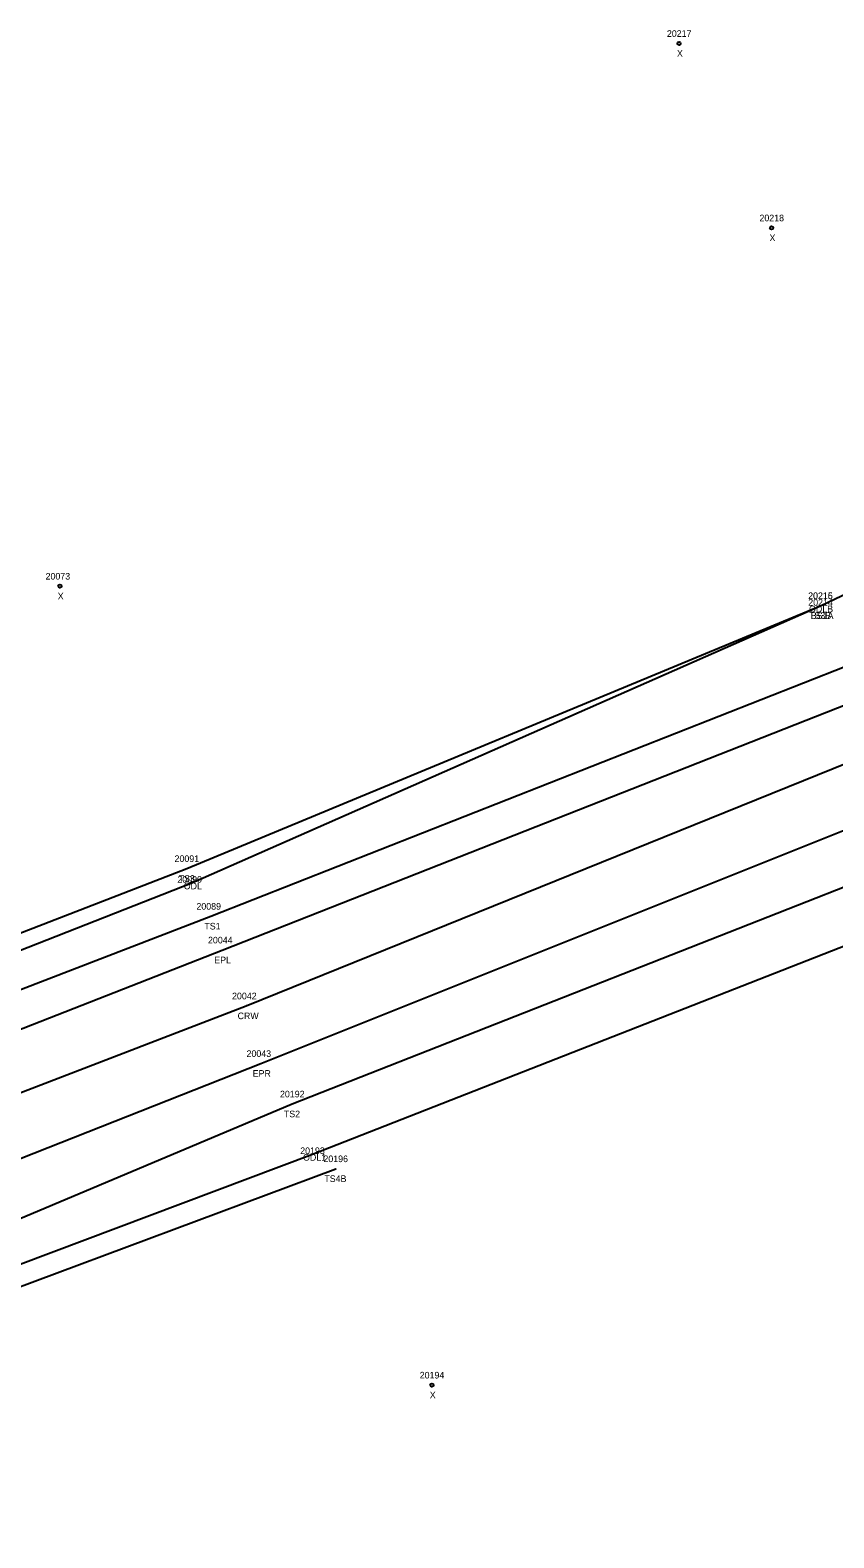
# Model space of a CAD drawing. Extents: x 1966740 to 1969291, y 1117378 to 1118461.
# Drawn here: x 1967441.2 to 1967562.8, y 1117652.7 to 1117880.7 of the extents above; entities that cross this region are included whole.
import ezdxf

# ---------------------------------------------------------------- set-up
doc = ezdxf.new("R2010")
doc.units = 0
for name, color, linetype in [('RD_DTM_BkLn1', 7, 'Continuous'), ('RD_DTM_BkLn2', 7, 'Continuous'), ('RD_EX_H2O', 7, 'Continuous'), ('RD_EX_H2O_txCode', 7, 'Continuous'), ('RD_EX_Road', 7, 'Continuous'), ('RD_EX_Road_txCode', 7, 'Continuous'), ('RD_SMD_Locator', 7, 'Continuous'), ('RD_SMD_Misc', 7, 'Continuous')]:
    doc.layers.add(name, color=color, linetype=linetype)

msp = doc.modelspace()

# ---------------------------------------------------------------- linework, layer by layer
at = {"layer": 'RD_DTM_BkLn1'}
msp.add_lwpolyline([(1966772.57, 1117449.88), (1966874.49, 1117489.87), (1966974.64, 1117529.93), (1967075.06, 1117571.68), (1967175.91, 1117613.34), (1967274.11, 1117653.69), (1967325.25, 1117674.8), (1967374.73, 1117695), (1967473.9, 1117733.1), (1967569.8, 1117771.9), (1967665.19, 1117809.79), (1967697.89, 1117822.8)], dxfattribs=at)
at = {"layer": 'RD_DTM_BkLn2'}
for points in [[(1967560.73, 1117793.63), (1967650.63, 1117836.46), (1967680.95, 1117850.94), (1967690.95, 1117852.56), (1967700.5, 1117839.06)], [(1966768.15, 1117461.43), (1966869.41, 1117499.34), (1967070.52, 1117582.35), (1967171.25, 1117624.02), (1967269.74, 1117664.9), (1967320.21, 1117685.71), (1967369.37, 1117708.48), (1967468.51, 1117746.66), (1967564.6, 1117784.47), (1967654.68, 1117828.05), (1967680.1, 1117841.48), (1967687.91, 1117842.93), (1967691.45, 1117838.71), (1967693.03, 1117834.22)], [(1967334.06, 1117655.75), (1967334.81, 1117659.44), (1967379.1, 1117675.46), (1967480.83, 1117718.27), (1967577.81, 1117756.42), (1967702.07, 1117801.85), (1967703.17, 1117805.75), (1967702.89, 1117809.87)], [(1966766.42, 1117472.19), (1966865.47, 1117508.82), (1967066.64, 1117593.45), (1967166.55, 1117636.11), (1967264.62, 1117677.56), (1967315.66, 1117698.57), (1967367.9, 1117716.34), (1967464.92, 1117753.87), (1967560.73, 1117793.63)], [(1967334.06, 1117655.75), (1967336.84, 1117652.84), (1967381.99, 1117669.13), (1967487.42, 1117708.48)]]:
    msp.add_lwpolyline(points, dxfattribs=at)
at = {"layer": 'RD_EX_H2O'}
for points in [[(1966766.64, 1117466.58), (1966867.24, 1117504.5), (1967068.76, 1117586.41), (1967167.95, 1117632.67), (1967266.82, 1117671.88), (1967316.79, 1117693.47), (1967368.01, 1117713.34), (1967465.67, 1117751.74), (1967560.73, 1117793.63)], [(1967336.04, 1117656.91), (1967380.56, 1117671.84), (1967483.89, 1117710.7), (1967580.8, 1117748.62), (1967673.4, 1117777.22)]]:
    msp.add_lwpolyline(points, dxfattribs=at)
at = {"layer": 'RD_EX_Road'}
for points in [[(1966769.51, 1117457.48), (1966870.16, 1117497.34), (1966971.19, 1117538.95), (1967071.09, 1117580.24), (1967172.6, 1117621.53), (1967270.79, 1117661.66), (1967321.12, 1117682.57), (1967371.52, 1117702.88), (1967470.26, 1117741.55), (1967566.67, 1117779.5), (1967661.25, 1117817.53), (1967694.4, 1117831.19), (1967697.89, 1117822.8)], [(1967340.03, 1117669.86), (1967379.26, 1117686.2), (1967476.09, 1117724.39), (1967573.92, 1117763.51), (1967667.7, 1117800.74), (1967701.64, 1117814), (1967697.89, 1117822.8)]]:
    msp.add_lwpolyline(points, dxfattribs=at)
at = {"layer": 'RD_SMD_Locator'}
for centre, radius in [((1967539.35, 1117878.65), 0.25), ((1967553.36, 1117850.76), 0.25), ((1967445.69, 1117796.58), 0.25), ((1967560.73, 1117793.63), 0.001), ((1967560.73, 1117793.63), 0.001), ((1967560.73, 1117793.63), 0.001), ((1967464.92, 1117753.87), 0.001), ((1967465.67, 1117751.74), 0.001), ((1967468.51, 1117746.66), 0.001), ((1967470.26, 1117741.55), 0.001), ((1967473.9, 1117733.1), 0.001), ((1967476.09, 1117724.39), 0.001), ((1967480.83, 1117718.27), 0.001), ((1967483.89, 1117710.7), 0.001), ((1967487.42, 1117708.48), 0.001), ((1967501.97, 1117675.76), 0.25)]:
    msp.add_circle(centre, radius, dxfattribs=at)

# ---------------------------------------------------------------- texts
at = {"layer": 'RD_EX_H2O_txCode'}
for s, p in [('20214', (1967558.9, 1117793.63)), ('ODLB', (1967559.02, 1117792.63)), ('20090', (1967463.47, 1117751.74)), ('ODL', (1967464.43, 1117750.74)), ('20193', (1967482.05, 1117710.7)), ('ODL1', (1967482.48, 1117709.7))]:
    msp.add_text(s, height=1, dxfattribs=at).set_placement(p)
at = {"layer": 'RD_EX_Road_txCode'}
for s, p in [('20044', (1967468.1, 1117742.55)), ('EPL', (1967469.05, 1117739.55)), ('20043', (1967473.93, 1117725.39)), ('EPR', (1967474.86, 1117722.39))]:
    msp.add_text(s, height=1, dxfattribs=at).set_placement(p)
at = {"layer": 'RD_SMD_Misc'}
for s, p in [('20217', (1967537.52, 1117879.65)), ('X', (1967539.04, 1117876.65)), ('20218', (1967551.52, 1117851.76)), ('X', (1967553.04, 1117848.76)), ('20073', (1967443.53, 1117797.58)), ('X', (1967445.37, 1117794.58)), ('20216', (1967558.88, 1117794.63)), ('20215', (1967558.9, 1117794.63)), ('TS3B', (1967559.02, 1117791.63)), ('BS1A', (1967559.3, 1117791.63)), ('20091', (1967463.04, 1117754.87)), ('TS3', (1967463.67, 1117751.87)), ('20089', (1967466.35, 1117747.66)), ('TS1', (1967467.55, 1117744.66)), ('20042', (1967471.74, 1117734.1)), ('CRW', (1967472.58, 1117731.1)), ('20192', (1967478.99, 1117719.27)), ('TS2', (1967479.58, 1117716.27)), ('20196', (1967485.56, 1117709.48)), ('TS4B', (1967485.7, 1117706.48)), ('20194', (1967500.13, 1117676.76)), ('X', (1967501.65, 1117673.76))]:
    msp.add_text(s, height=1, dxfattribs=at).set_placement(p)

doc.saveas('drawing.dxf')
